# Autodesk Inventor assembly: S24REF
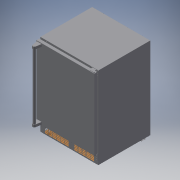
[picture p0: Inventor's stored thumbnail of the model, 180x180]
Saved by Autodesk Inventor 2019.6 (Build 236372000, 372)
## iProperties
Created: 2025-05
Part Number: S24REF
Document SubType Name: Assembly
Designer: MMAK
Title: S24REF
Revision Number: AFirst version
Sending System: Rhino 8.18
Preprocessor: ST-DEVELOPER v19.2
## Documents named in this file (3)
- C:\Users\MMAK\Documents\SmarTeam\WEBSITE CAD\S24REF\S24REF.iam
- C:\Users\MMAK\Documents\SmarTeam\WEBSITE CAD\S24REF\S24REF.stp.iam
- S24REF.stp
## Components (1 placed, 1 different names)
1. S24REF [sub-assembly]
